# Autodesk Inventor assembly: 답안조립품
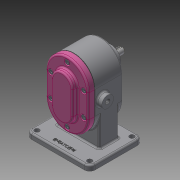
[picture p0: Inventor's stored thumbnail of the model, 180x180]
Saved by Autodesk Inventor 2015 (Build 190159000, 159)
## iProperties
Created: 2020-09
Part Number: 답안조립품
Document SubType Name: 용접물
Designer: Lineart
Weld Material: 알루미늄 6061, 용접
Author: Lineart
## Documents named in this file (11)
- C:\Users\Lineart\Desktop\700906V1041\답안조립품.iam
- C:\Users\Lineart\Desktop\700906V1041\본체.ipt
- C:\Users\Lineart\Desktop\700906V1041\베어링부시.ipt
- C:\Users\Lineart\Desktop\700906V1041\메인축.ipt
- C:\Users\Lineart\Desktop\700906V1041\오일 실 16 28 7.ipt
- C:\Users\Lineart\Desktop\700906V1041\키 6 x 6 x 18.ipt
- C:\Users\Lineart\Desktop\700906V1041\스퍼기어.ipt
- C:\Users\Lineart\Desktop\700906V1041\서브축.ipt
- C:\Users\Lineart\Desktop\700906V1041\커버.ipt
- C:\Users\Lineart\Desktop\700906V1041\개스킷.ipt
- C:\Users\Lineart\Desktop\700906V1041\볼트 M5.ipt
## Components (1 placed, 1 different names)
1. 개스킷:1
